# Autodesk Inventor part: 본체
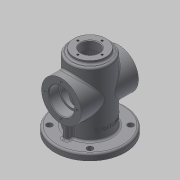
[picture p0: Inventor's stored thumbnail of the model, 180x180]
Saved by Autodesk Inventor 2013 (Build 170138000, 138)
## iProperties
Created: 2020-05
Part Number: 본체
Material: 일반
Document SubType Name: Modeling
Designer: mduedu
Density: 1 g/cm^3
Author: mduedu
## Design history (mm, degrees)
sketch "스케치1"
  geometry: C1 r 32 at (0, 0); 1 further point
  constraints: 1 centre point, 1 coincident
  dimensions: "d0" = 64 diameter of C1
extrude "돌출1" new body sketch "스케치1" distance "d1" = 110; taper "d2" = 0 deg
feature "쉘1" dims "d3" = 8
fillet "모깎기1" dims "d4" = 3
fillet "모깎기2" dims "d5" = 3
sketch "스케치2"
  geometry: C1 r 25 at (0, 0); 1 further point
  constraints: 1 centre point, 1 coincident
  dimensions: "d6" = 50 diameter of C1
extrude "돌출2" join sketch "스케치2" distance "d7" = 5; taper "d8" = 0 deg
sketch "스케치3"
  geometry: C1 r 14 at (0, 0); 1 further point
  constraints: 1 centre point, 1 coincident
  dimensions: "d9" = 28 diameter of C1
extrude "돌출3" cut sketch "스케치3" stored distance "d10" = 5; taper "d11" = 0 deg
fillet "모깎기3" dims "d12" = 3
sketch "스케치4"
  geometry: C1 r 32 at (0, 0) reference; C2 r 55 at (0, 0); 1 further point
  constraints: 1 centre point, 1 coincident
  dimensions: "d13" = 110 diameter of C2
extrude "돌출4" join sketch "스케치4" distance "d14" = 10; taper "d15" = 0 deg
sketch "스케치5"
  geometry: L1 (0, 0)-(-31.82, 31.82); L2 (0, 0)-(-45, 0); A1 r 45 centre (0, 0) between (-31.82, 31.82) and (-45, 0); 1 further point
  constraints: 4 end point, 2 point on circle, 1 centre point, 1 coincident, 1 horizontal
  dimensions: "d16" = 90 diameter of A1; "d71" = 45 deg angle of L1 L2
hole "구멍1" sketch "스케치5" at (-31.82, 31.82) diameter "d17" = 9; stored, may be unused: countersink angle "d21" = 90 deg, drill point angle "d23" = 118 deg; dims "d18" = 6, "d19" = 4, "d20" = 2, "d22" = 8
fillet "모깎기4" dims "d27" = 3
node "작업 평면1"
sketch "스케치6"
  geometry: L1 (0, 55)-(0, -55) reference; C1 r 31 at (-65, 0); 2 further points
  constraints: 1 centre point, 1 horizontal alignment, 1 midpoint
  dimensions: "d31" = 62 diameter of C1; "d32" = 65 distance from line of C1.centre L1
extrude "돌출5" join sketch "스케치6" stored distance "d33" = 10; taper "d34" = 0 deg
fillet "모깎기5" dims "d35" = 3
sketch "스케치7"
  geometry: C1 r 31 at (0, 0) reference; C2 r 20 at (0, 0); 1 further point
  constraints: 1 centre point, 1 coincident
  dimensions: "d36" = 40 diameter of C2
extrude "돌출6" cut sketch "스케치7" distance "d37" = 16; taper "d38" = 0 deg
sketch "스케치8"
  geometry: C1 r 20 at (0, 0) reference; C2 r 17 at (0, 0); 1 further point
  constraints: 1 centre point, 1 coincident
  dimensions: "d39" = 34 diameter of C2
extrude "돌출7" cut sketch "스케치8" stored distance "d40" = 15; taper "d41" = 0 deg
fillet "모깎기6" dims "d42" = 0.3
chamfer "모따기1" distance "d43" = 1; stored, may be unused: second distance "d44" = 2, angle "d45" = 45 deg
chamfer "모따기2" distance "d46" = 1; stored, may be unused: second distance "d47" = 2, angle "d48" = 45 deg
sketch "스케치9" dims "d49" = 50
  geometry: C1 r 31 at (0, 0) reference; 3 further points
  constraints: 2 vertical alignment, 1 coincident, 2 other
hole "구멍2" sketch "스케치9" at (0, 25) diameter "d50" = 3.242; stored, may be unused: countersink angle "d54" = 90 deg, drill point angle "d56" = 118 deg; dims "d51" = 7, "d52" = 4, "d53" = 2, "d55" = 9
sketch "스케치10" dims "d60" = 38
  geometry: 3 further points
  constraints: 2 vertical alignment, 1 coincident, 2 other
hole "구멍3" sketch "스케치10" at (0, 19) diameter "d61" = 3.242; stored, may be unused: countersink angle "d65" = 90 deg, drill point angle "d67" = 118 deg; dims "d62" = 8, "d63" = 4, "d64" = 2, "d66" = 10
sketch "스케치11"
  geometry: L1 (32, 31)-(32, 13) reference; L2 (35, 10)-(52, 10) reference; L3 (55, 7)-(55, 0) reference; L4 (55, 0)-(24, 0) reference; L5 (24, 0)-(24, 48) reference; L6 (24, 48)-(29, 48) reference; L7 (29, 48)-(29, 45.3) reference; L8 (29.3, 45)-(44, 45) reference; L9 (44, 45)-(45, 44) reference; L10 (45, 44)-(45, 41.621) reference; L11 (45, 41.621)-(36, 41.621) reference; L12 (36, 41.621)-(35.026, 40) reference; L13 (35.026, 40)-(36, 38.379) reference; L14 (36, 38.379)-(45, 38.379) reference; L15 (45, 38.379)-(45, 34) reference; L16 (45, 34)-(35, 34) reference; L17 (-32, 13)-(-32, 31) reference; L18 (-35, 34)-(-45, 34) reference; L19 (-45, 34)-(-45, 38.379) reference; L20 (-45, 38.379)-(-36, 38.379) reference; L21 (-36, 38.379)-(-35.026, 40) reference; L22 (-35.026, 40)-(-36, 41.621) reference; L23 (-36, 41.621)-(-45, 41.621) reference; L24 (-45, 41.621)-(-45, 44) reference; L25 (-45, 44)-(-44, 45) reference; L26 (-44, 45)-(-29.3, 45) reference; L27 (-29, 45.3)-(-29, 48) reference; L28 (-29, 48)-(-24, 48) reference; L29 (-24, 48)-(-24, 0) reference; L30 (-24, 0)-(-55, 0) reference; L31 (-55, 0)-(-55, 7) reference; L32 (-52, 10)-(-35, 10) reference; L33 (-25, 113)-(-25, 115) reference; L34 (-25, 115)-(-20.621, 115) reference; L35 (-20.621, 115)-(-20.621, 105) reference; L36 (-20.621, 105)-(-19, 104.026) reference; L37 (-19, 104.026)-(-17.379, 105) reference; L38 (-17.379, 105)-(-17.379, 115) reference; L39 (-17.379, 115)-(-15, 115) reference; L40 (-15, 115)-(-14, 114) reference; L41 (-14, 114)-(-14, 102) reference; L42 (-14, 102)-(-21, 102) reference; L43 (-24, 99)-(-24, 82) reference; L44 (-24, 82)-(-29, 82) reference; L45 (-29, 82)-(-29, 84.7) reference; L46 (-29.3, 85)-(-44, 85) reference; L47 (-44, 85)-(-45, 86) reference; L48 (-45, 86)-(-45, 88.379) reference; L49 (-45, 88.379)-(-36, 88.379) reference; L50 (-36, 88.379)-(-35.026, 90) reference; L51 (-35.026, 90)-(-36, 91.621) reference; L52 (-36, 91.621)-(-45, 91.621) reference; L53 (-45, 91.621)-(-45, 96) reference; L54 (-45, 96)-(-35, 96) reference; L55 (-32, 99)-(-32, 107) reference; L56 (-29, 110)-(-28, 110) reference; L57 (28, 110)-(29, 110) reference; L58 (32, 107)-(32, 99) reference; L59 (35, 96)-(45, 96) reference; L60 (45, 96)-(45, 91.621) reference; L61 (45, 91.621)-(36, 91.621) reference; L62 (36, 91.621)-(35.026, 90) reference; L63 (35.026, 90)-(36, 88.379) reference; L64 (36, 88.379)-(45, 88.379) reference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; A1 r 3 centre (35, 13) between (32, 13) and (35, 10) reference; A2 r 3 centre (52, 7) between (55, 7) and (52, 10) reference; A3 r 0.3 centre (29.3, 45.3) between (29, 45.3) and (29.3, 45) reference; A4 r 0.3 centre (-29.3, 45.3) between (-29.3, 45) and (-29, 45.3) reference; A5 r 3 centre (-52, 7) between (-52, 10) and (-55, 7) reference; A6 r 3 centre (-35, 13) between (-35, 10) and (-32, 13) reference; A7 r 3 centre (-28, 113) between (-28, 110) and (-25, 113) reference; A8 r 3 centre (-21, 99) between (-21, 102) and (-24, 99) reference; A9 r 0.3 centre (-29.3, 84.7) between (-29, 84.7) and (-29.3, 85) reference; A10 r 3 centre (-29, 107) between (-29, 110) and (-32, 107) reference; A11 r 3 centre (28, 113) between (25, 113) and (28, 110) reference; A12 r 3 centre (29, 107) between (32, 107) and (29, 110) reference; A13 r 0.3 centre (29.3, 84.7) between (29.3, 85) and (29, 84.7) reference; A14 r 3 centre (21, 99) between (24, 99) and (21, 102) reference; 1 further point
  constraints: 2 end point, 1 midpoint, 1 perpendicular, 1 point on line, 4 other
  dimensions: "d73" = 5 distance between parallel lines of L81 L19
feature "리브1" sketch "스케치11" dims "d74" = 1, "d75" = 8, "d76" = 0, "d77" = 0, "d78" = 1, "d79" = 1
fillet "모깎기7" dims "d80" = 3
fillet "모깎기8" dims "d81" = 3
node "작업 평면2"
sketch "스케치12"
  geometry: 2 further points
  constraints: 1 vertical alignment, 1 other
  dimensions: "d83" = 25 distance of point (0, 25) point (0, 0)
feature "엠보싱1" sketch "스케치12" dims "d0" = 64, "d84" = 0.5, "d85" = 0
node "솔리드1"
pattern_circular "원형 패턴1" dims angle "d25" = 360 deg
mirror "대칭1"
mirror "대칭2"
pattern_circular "원형 패턴2" dims angle "d58" = 360 deg
mirror "대칭3"
pattern_circular "원형 패턴3" dims angle "d69" = 360 deg
mirror "대칭4"
node "투영된 루프1"
node "투영된 루프2"
node "절단 모서리 투영1"
other parameters: "d30" = -45
